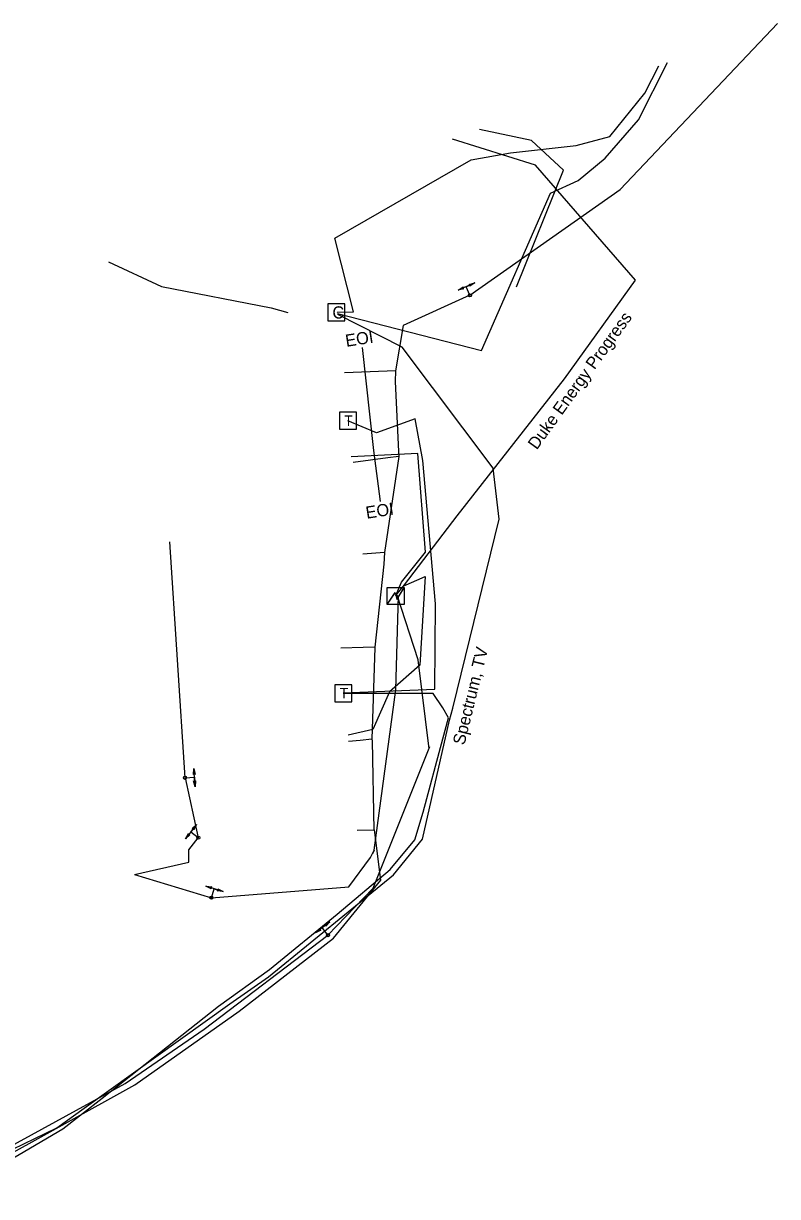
# Model space of a CAD drawing. Extents: x 2070721 to 2083039, y 729290 to 737883.
# Drawn here: x 2080279.4 to 2080526.8, y 734985.4 to 735370.3 of the extents above; entities that cross this region are included whole.
import ezdxf

# ---------------------------------------------------------------- set-up
doc = ezdxf.new("R2010")
doc.units = 0
for name, color, linetype in [('Cogo Default Point CELL', 7, 'Continuous'), ('Exist Utilities Power Pole Cogo Elevation', 7, 'Continuous'), ('Exist Utilities Power UG Cable Cogo Point CELL', 7, 'Continuous'), ('Exist Utilities Power UG Cable SUE LOS B Cogo Comment', 7, 'Continuous'), ('Exist Utilities Telephone Hand Hole Cogo Elevation', 7, 'Continuous'), ('Exist Utilities Telephone UG Cable SUE LOS C Cogo Comment', 7, 'Continuous'), ('Exist Utilities Telephone UG Cable SUE LOS C Cogo Number', 7, 'Continuous'), ('Exist Utilities Telephone UG FO SUE LOS B Cogo Comment', 7, 'Continuous'), ('Exist Utilities TV Pedestal Cogo Elevation', 7, 'Continuous'), ('Exist Utilities TV Pedestal Cogo Number', 7, 'Continuous'), ('Exist Utilities TV UG Cable Cogo Point CELL', 7, 'Continuous'), ('Exist Utilities TV UG Cable SUE LOS C Cogo Comment', 7, 'Continuous'), ('Exist Utilities TV UG Cable SUE LOS C Cogo Elevation', 7, 'Continuous'), ('Exist Utilities TV UG FO Cable SUE Cogo Point CELL', 7, 'Continuous'), ('Exist Utilities TV UG FO Cable SUE LOS B Cogo Comment', 7, 'Continuous'), ('Exist Utilities Water Meter CELL', 7, 'Continuous')]:
    doc.layers.add(name, color=color, linetype=linetype)

msp = doc.modelspace()

# ---------------------------------------------------------------- linework, layer by layer
at = {"layer": 'Cogo Default Point CELL'}
msp.add_line((2080382.09, 735275.47), (2080382.09, 735275.47), dxfattribs=at)
msp.add_lwpolyline([(2080379.32, 735272.7), (2080384.87, 735272.7), (2080384.87, 735278.25), (2080379.32, 735278.25), (2080379.32, 735272.7)], dxfattribs=at)
at = {"layer": 'Exist Utilities Power Pole Cogo Elevation'}
for p, q in [((2080332.43, 735122.8), (2080327.44, 735200.23)), ((2080315.9, 735091.11), (2080341.08, 735083.44))]:
    msp.add_line(p, q, dxfattribs=at)
for points in [[(2080441.2, 735283.91), (2080456.62, 735322.11), (2080446.12, 735331.85), (2080429.09, 735335.47)], [(2080315.9, 735091.11), (2080333.69, 735095.06), (2080333.69, 735099.1), (2080336.76, 735103.12)], [(2080184.91, 735034.97), (2080213.27, 734992.91), (2080223.08, 734985.41), (2080235.33, 734985.41), (2080274.11, 735001.25), (2080312.76, 735022.46), (2080338.71, 735040.35), (2080379.32, 735071.17)]]:
    msp.add_lwpolyline(points, dxfattribs=at)
at = {"layer": 'Exist Utilities Power UG Cable Cogo Point CELL'}
for p, q in [((2080335.71, 735119.86), (2080335.33, 735125.81)), ((2080332.43, 735122.8), (2080335.51, 735122.99)), ((2080332.43, 735122.8), (2080332.43, 735122.8)), ((2080335.51, 735122.99), (2080335.71, 735119.86)), ((2080336.21, 735107.48), (2080332.59, 735102.74)), ((2080334.31, 735104.99), (2080336.21, 735107.48)), ((2080336.76, 735103.12), (2080334.31, 735104.99)), ((2080336.76, 735103.12), (2080336.76, 735103.12)), ((2080344.98, 735085.47), (2080339.28, 735087.21)), ((2080341.08, 735083.44), (2080341.98, 735086.39)), ((2080341.08, 735083.44), (2080341.08, 735083.44)), ((2080341.98, 735086.39), (2080344.98, 735085.47)), ((2080379.95, 735075.53), (2080375.2, 735071.92)), ((2080377.45, 735073.63), (2080379.95, 735075.53)), ((2080379.32, 735071.17), (2080377.45, 735073.63)), ((2080379.32, 735071.17), (2080379.32, 735071.17))]:
    msp.add_line(p, q, dxfattribs=at)
for points in [[(2080335.33, 735125.81), (2080335.8, 735123.87), (2080335.43, 735124.27), (2080335.15, 735123.87)], [(2080335.71, 735119.86), (2080335.24, 735121.81), (2080335.61, 735121.41), (2080335.89, 735121.81)], [(2080336.21, 735107.48), (2080335.29, 735105.71), (2080335.27, 735106.25), (2080334.79, 735106.13)], [(2080332.59, 735102.74), (2080333.51, 735104.52), (2080333.53, 735103.97), (2080334.01, 735104.09)], [(2080339.28, 735087.21), (2080341.27, 735086.97), (2080340.76, 735086.76), (2080341.04, 735086.36)], [(2080344.98, 735085.47), (2080343, 735085.72), (2080343.5, 735085.93), (2080343.22, 735086.33)], [(2080379.95, 735075.53), (2080378.59, 735074.06), (2080378.72, 735074.59), (2080378.23, 735074.6)], [(2080375.2, 735071.92), (2080376.56, 735073.39), (2080376.44, 735072.86), (2080376.93, 735072.85)]]:
    msp.add_lwpolyline(points, close=True, dxfattribs=at)
for centre in [(2080332.43, 735122.8), (2080336.76, 735103.12), (2080341.08, 735083.44), (2080379.32, 735071.17)]:
    msp.add_circle(centre, 0.517, dxfattribs=at)
at = {"layer": 'Exist Utilities Power UG Cable SUE LOS B Cogo Comment'}
for p, q in [((2080427.49, 735285.18), (2080422.06, 735282.72)), ((2080424.64, 735283.89), (2080427.49, 735285.18)), ((2080425.91, 735281.08), (2080424.64, 735283.89)), ((2080425.91, 735281.08), (2080425.91, 735281.08))]:
    msp.add_line(p, q, dxfattribs=at)
for points in [[(2080422.06, 735282.72), (2080423.71, 735283.85), (2080423.47, 735283.36), (2080423.95, 735283.24)], [(2080427.49, 735285.18), (2080425.84, 735284.06), (2080426.08, 735284.54), (2080425.61, 735284.67)]]:
    msp.add_lwpolyline(points, close=True, dxfattribs=at)
msp.add_circle((2080425.91, 735281.08), 0.517, dxfattribs=at)
at = {"layer": 'Exist Utilities Telephone UG Cable SUE LOS C Cogo Comment'}
msp.add_lwpolyline([(2080390.53, 735263.96), (2080394.31, 735230.13), (2080396.49, 735213.47)], dxfattribs=at)
at = {"layer": 'Exist Utilities Telephone UG Cable SUE LOS C Cogo Number'}
msp.add_line((2080401.57, 735182.62), (2080401.57, 735182.62), dxfattribs=at)
msp.add_lwpolyline([(2080398.72, 735185.24), (2080404.27, 735185.24), (2080404.27, 735179.68), (2080398.72, 735179.68)], close=True, dxfattribs=at)
for points in [[(2080398.72, 735179.68), (2080401.37, 735183.63), (2080401.99, 735181.42), (2080404.27, 735185.24)], [(2080398.79, 735179.68), (2080401.37, 735183.42), (2080401.95, 735181.24), (2080404.27, 735185.08)]]:
    msp.add_lwpolyline(points, dxfattribs=at)
at = {"layer": 'Exist Utilities Telephone UG FO SUE LOS B Cogo Comment'}
for p, q in [((2080385.79, 735239.95), (2080385.79, 735239.95)), ((2080384.31, 735150.56), (2080384.31, 735150.56))]:
    msp.add_line(p, q, dxfattribs=at)
for points in [[(2080383.07, 735237.12), (2080388.66, 735237.12), (2080388.66, 735242.72), (2080383.07, 735242.72), (2080383.07, 735237.12)], [(2080381.59, 735147.74), (2080387.18, 735147.74), (2080387.18, 735153.33), (2080381.59, 735153.33), (2080381.59, 735147.74)]]:
    msp.add_lwpolyline(points, dxfattribs=at)
at = {"layer": 'Exist Utilities TV Pedestal Cogo Elevation'}
msp.add_lwpolyline([(2080307.31, 735292.11), (2080324.7, 735284.01), (2080360.73, 735276.97), (2080366.17, 735275.47)], dxfattribs=at)
at = {"layer": 'Exist Utilities TV Pedestal Cogo Number'}
msp.add_line((2080397.88, 735196.69), (2080390.75, 735196.19), dxfattribs=at)
for points in [[(2080425.91, 735281.08), (2080403.96, 735271.14), (2080401.43, 735256.34)], [(2080401.43, 735256.34), (2080398.73, 735256.24), (2080384.69, 735255.67)], [(2080401.43, 735256.34), (2080401.37, 735252.76), (2080402.5, 735229.83), (2080402.55, 735228.15)], [(2080402.55, 735228.15), (2080399.01, 735227.73), (2080387.55, 735226.22)], [(2080402.55, 735228.15), (2080397.88, 735196.69)], [(2080397.88, 735196.69), (2080397.62, 735192.92), (2080394.69, 735165.62)], [(2080394.69, 735165.62), (2080390.87, 735165.52), (2080383.56, 735165.33)], [(2080394.7, 735165.52), (2080393.67, 735135.42)], [(2080393.67, 735135.42), (2080389.85, 735135.05), (2080386.03, 735134.67)], [(2080393.67, 735135.42), (2080393.83, 735134.93), (2080394.41, 735105.63), (2080388.9, 735105.46)], [(2080265, 734993.65), (2080268.16, 734995.62), (2080315.96, 735022.08), (2080350.22, 735046.21), (2080381.14, 735070.17), (2080396.65, 735089.25), (2080394.64, 735105.68)]]:
    msp.add_lwpolyline(points, dxfattribs=at)
at = {"layer": 'Exist Utilities TV UG Cable Cogo Point CELL'}
for points in [[(2080384.26, 735150.63), (2080414.34, 735151.9), (2080414.62, 735179.86), (2080410.46, 735226.87), (2080407.97, 735240.56), (2080395.27, 735235.94), (2080385.85, 735239.88)], [(2080258.12, 734995.23), (2080263.29, 734994.32), (2080269.47, 734994.32), (2080277.96, 734999.19), (2080292.29, 735007.6), (2080305.23, 735017.65), (2080343.43, 735047.82), (2080360.16, 735059.94), (2080382.3, 735078.07), (2080399.75, 735092.65), (2080407.82, 735102.46), (2080410.57, 735111.53), (2080417.01, 735135.56), (2080418.86, 735142.51), (2080417.06, 735145.72), (2080413.79, 735150.42), (2080384.27, 735150.47)]]:
    msp.add_lwpolyline(points, dxfattribs=at)
at = {"layer": 'Exist Utilities TV UG Cable SUE LOS C Cogo Comment'}
for points in [[(2080401.57, 735182.62), (2080404.41, 735186.14), (2080421.75, 735208.75), (2080456.92, 735253.65), (2080480.26, 735286.05), (2080447.38, 735323.81), (2080420.2, 735332.31)], [(2080401.57, 735182.62), (2080403.45, 735187.01), (2080411.27, 735196.77), (2080408.82, 735229.21), (2080386.88, 735228.1)], [(2080403.98, 735185.66), (2080411.17, 735188.81), (2080409.41, 735159.72), (2080399.49, 735151.03), (2080394.08, 735138.67), (2080386, 735136.79)], [(2080394.53, 735099.01), (2080401.54, 735151.67), (2080402.47, 735182.6)], [(2080412.55, 735132.28), (2080408.94, 735161.49), (2080401.98, 735182.69)], [(2080412.59, 735132.94), (2080394.09, 735086.48), (2080379.32, 735071.17)], [(2080332.43, 735122.8), (2080336.76, 735103.12)], [(2080341.08, 735083.44), (2080386.18, 735087.05), (2080393.23, 735096.68), (2080394.53, 735099.01), (2080393.88, 735097.84)]]:
    msp.add_lwpolyline(points, dxfattribs=at)
at = {"layer": 'Exist Utilities TV UG Cable SUE LOS C Cogo Elevation'}
for points in [[(2080382.32, 735275.51), (2080387.67, 735275.64), (2080381.57, 735299.83), (2080426.26, 735325.54), (2080439.21, 735327.78), (2080460.7, 735330.21), (2080471.81, 735333.16), (2080483.32, 735347.41), (2080487.9, 735356.41)], [(2080382.49, 735275.17), (2080429.65, 735262.94), (2080452.36, 735314.62), (2080461.36, 735318.73), (2080470.3, 735326.03), (2080481.2, 735338.62), (2080490.75, 735357.43)], [(2080420.28, 735145.67), (2080435.53, 735207.68), (2080433.57, 735224.41), (2080403.63, 735264.05), (2080382.55, 735274.81)], [(2080359.81, 735057.53), (2080400.79, 735090.94), (2080410.35, 735102.61), (2080419.18, 735141.68), (2080420.28, 735145.67)], [(2080259.06, 735072.37), (2080251.03, 735055.15), (2080258.34, 735010.88), (2080268.58, 734997.41), (2080290.37, 735007.91), (2080299.29, 735014.42), (2080347.12, 735048.66), (2080359.81, 735057.53)]]:
    msp.add_lwpolyline(points, dxfattribs=at)
at = {"layer": 'Exist Utilities TV UG FO Cable SUE Cogo Point CELL'}
msp.add_lwpolyline([(2080425.91, 735281.08), (2080475.14, 735315.78), (2080526.82, 735370.27)], dxfattribs=at)

# ---------------------------------------------------------------- texts
at = {"layer": 'Cogo Default Point CELL'}
msp.add_text('C', height=4, dxfattribs=at).set_placement((2080380.78, 735273.47))
at = {"layer": 'Exist Utilities Telephone Hand Hole Cogo Elevation'}
msp.add_text('Spectrum, TV ', height=4, rotation=76.1827, dxfattribs=at).set_placement((2080424.08, 735133.32))
at = {"layer": 'Exist Utilities Telephone UG FO SUE LOS B Cogo Comment'}
for p in [(2080384.66, 735238.24), (2080383.18, 735148.85)]:
    msp.add_text('T', height=3.42, dxfattribs=at).set_placement(p)
at = {"layer": 'Exist Utilities TV UG FO Cable SUE LOS B Cogo Comment'}
for p in [(2080385.35, 735264.16), (2080392.03, 735207.75)]:
    msp.add_text('EOI', height=4, rotation=8.9445, dxfattribs=at).set_placement(p)
at = {"layer": 'Exist Utilities Water Meter CELL'}
msp.add_text('Duke Energy Progress', height=4, rotation=54.2195, dxfattribs=at).set_placement((2080447.83, 735230.18))

doc.saveas('drawing.dxf')
